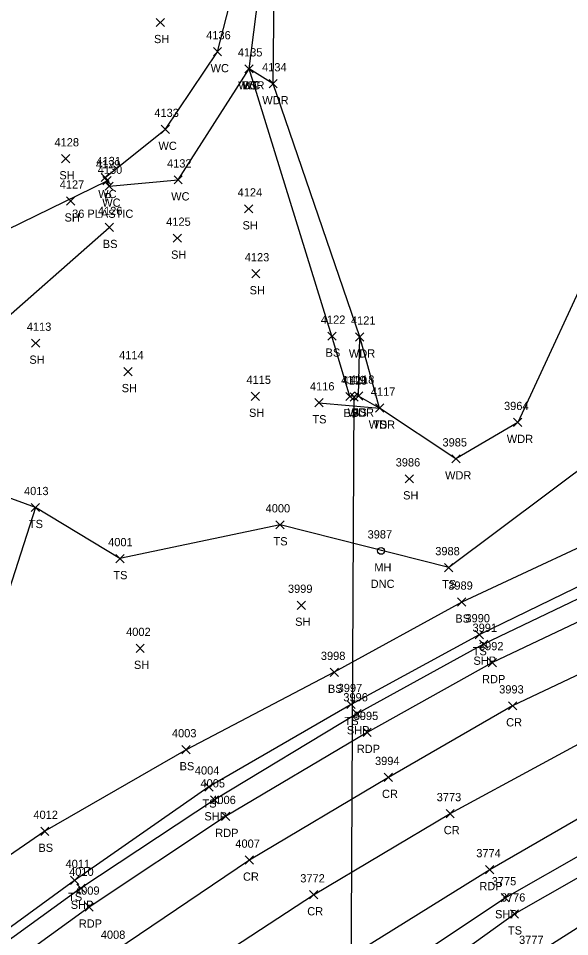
# Model space of a CAD drawing. Extents: x 1623612 to 1625808, y 621345 to 627748.
# Drawn here: x 1625217 to 1625350.8, y 627315.5 to 627538.2 of the extents above; entities that cross this region are included whole.
import ezdxf

# ---------------------------------------------------------------- set-up
doc = ezdxf.new("R2010")
doc.units = 0
for name, color, linetype in [('D_A', 7, 'Continuous'), ('D_C', 7, 'Continuous'), ('D_I', 7, 'Continuous'), ('D_TIC', 7, 'Continuous'), ('DCP', 7, 'Continuous'), ('L_A', 7, 'Continuous'), ('L_I', 7, 'Continuous'), ('L_TIC', 7, 'Continuous'), ('LAWA', 7, 'Continuous'), ('LAWE', 7, 'Continuous'), ('LELB', 7, 'Continuous'), ('LSOGP', 7, 'Continuous'), ('P_A', 7, 'Continuous'), ('P_I', 7, 'Continuous'), ('P_TIC', 7, 'Continuous'), ('PET', 7, 'Continuous'), ('PRC', 7, 'Continuous'), ('PSP', 7, 'Continuous'), ('U_A', 7, 'Continuous'), ('U_C', 7, 'Continuous'), ('U_I', 7, 'Continuous'), ('UUMH', 7, 'Continuous')]:
    doc.layers.add(name, color=color, linetype=linetype)

msp = doc.modelspace()

# ---------------------------------------------------------------- linework, layer by layer
at = {"layer": 'D_TIC'}
for points in [[(1625237.51, 627497.84), (1625239.51, 627499.84)], [(1625239.51, 627497.84), (1625237.51, 627499.84)], [(1625297.49, 627445.36), (1625299.49, 627447.36)], [(1625299.49, 627445.36), (1625297.49, 627447.36)]]:
    msp.add_lwpolyline(points, dxfattribs=at)
at = {"layer": 'DCP'}
for points in [[(1625062.29, 627412.82), (1625238.51, 627498.84)], [(1625297.51, 627253.9), (1625298.49, 627446.36)]]:
    msp.add_lwpolyline(points, dxfattribs=at)
at = {"layer": 'L_TIC'}
for points in [[(1625250.42, 627536.22), (1625252.42, 627538.22)], [(1625252.42, 627536.22), (1625250.42, 627538.22)], [(1625264.33, 627529.15), (1625266.33, 627531.15)], [(1625266.33, 627529.15), (1625264.33, 627531.15)], [(1625271.97, 627524.99), (1625273.97, 627526.99)], [(1625273.97, 627524.99), (1625271.97, 627526.99)], [(1625271.97, 627524.99), (1625273.97, 627526.99)], [(1625273.97, 627524.99), (1625271.97, 627526.99)], [(1625271.97, 627524.99), (1625273.97, 627526.99)], [(1625273.97, 627524.99), (1625271.97, 627526.99)], [(1625277.83, 627521.38), (1625279.83, 627523.38)], [(1625279.83, 627521.38), (1625277.83, 627523.38)], [(1625251.68, 627510.31), (1625253.68, 627512.31)], [(1625253.68, 627510.31), (1625251.68, 627512.31)], [(1625227.45, 627503.17), (1625229.45, 627505.17)], [(1625229.45, 627503.17), (1625227.45, 627505.17)], [(1625237.06, 627498.63), (1625239.06, 627500.63)], [(1625239.06, 627498.63), (1625237.06, 627500.63)], [(1625254.77, 627498.05), (1625256.77, 627500.05)], [(1625256.77, 627498.05), (1625254.77, 627500.05)], [(1625238.03, 627496.52), (1625240.03, 627498.52)], [(1625240.03, 627496.52), (1625238.03, 627498.52)], [(1625238.03, 627496.52), (1625240.03, 627498.52)], [(1625240.03, 627496.52), (1625238.03, 627498.52)], [(1625228.71, 627492.93), (1625230.71, 627494.93)], [(1625230.71, 627492.93), (1625228.71, 627494.93)], [(1625271.91, 627491.02), (1625273.91, 627493.02)], [(1625273.91, 627491.02), (1625271.91, 627493.02)], [(1625238.04, 627486.51), (1625240.04, 627488.51)], [(1625240.04, 627486.51), (1625238.04, 627488.51)], [(1625254.56, 627483.91), (1625256.56, 627485.91)], [(1625256.56, 627483.91), (1625254.56, 627485.91)], [(1625273.63, 627475.28), (1625275.63, 627477.28)], [(1625275.63, 627475.28), (1625273.63, 627477.28)], [(1625292.11, 627460.14), (1625294.11, 627462.14)], [(1625294.11, 627460.14), (1625292.11, 627462.14)], [(1625298.84, 627459.95), (1625300.84, 627461.95)], [(1625300.84, 627459.95), (1625298.84, 627461.95)], [(1625220.17, 627458.43), (1625222.17, 627460.43)], [(1625222.17, 627458.43), (1625220.17, 627460.43)], [(1625242.58, 627451.54), (1625244.58, 627453.54)], [(1625244.58, 627451.54), (1625242.58, 627453.54)], [(1625273.48, 627445.55), (1625275.48, 627447.55)], [(1625275.48, 627445.55), (1625273.48, 627447.55)], [(1625296.46, 627445.5), (1625298.46, 627447.5)], [(1625298.46, 627445.5), (1625296.46, 627447.5)], [(1625298.56, 627445.61), (1625300.56, 627447.61)], [(1625300.56, 627445.61), (1625298.56, 627447.61)], [(1625298.56, 627445.61), (1625300.56, 627447.61)], [(1625300.56, 627445.61), (1625298.56, 627447.61)], [(1625288.94, 627443.97), (1625290.94, 627445.97)], [(1625290.94, 627443.97), (1625288.94, 627445.97)], [(1625303.67, 627442.68), (1625305.67, 627444.68)], [(1625305.67, 627442.68), (1625303.67, 627444.68)], [(1625303.67, 627442.68), (1625305.67, 627444.68)], [(1625305.67, 627442.68), (1625303.67, 627444.68)], [(1625337.18, 627439.21), (1625339.18, 627441.21)], [(1625339.18, 627439.21), (1625337.18, 627441.21)], [(1625322.19, 627430.37), (1625324.19, 627432.37)], [(1625324.19, 627430.37), (1625322.19, 627432.37)], [(1625310.88, 627425.52), (1625312.88, 627427.52)], [(1625312.88, 627425.52), (1625310.88, 627427.52)], [(1625220.13, 627418.57), (1625222.13, 627420.57)], [(1625222.13, 627418.57), (1625220.13, 627420.57)], [(1625220.13, 627418.57), (1625222.13, 627420.57)], [(1625222.13, 627418.57), (1625220.13, 627420.57)], [(1625279.5, 627414.37), (1625281.5, 627416.37)], [(1625281.5, 627414.37), (1625279.5, 627416.37)], [(1625240.63, 627406.16), (1625242.63, 627408.16)], [(1625242.63, 627406.16), (1625240.63, 627408.16)], [(1625320.43, 627403.98), (1625322.43, 627405.98)], [(1625322.43, 627403.98), (1625320.43, 627405.98)], [(1625323.6, 627395.63), (1625325.6, 627397.63)], [(1625325.6, 627395.63), (1625323.6, 627397.63)], [(1625284.69, 627394.86), (1625286.69, 627396.86)], [(1625286.69, 627394.86), (1625284.69, 627396.86)], [(1625327.85, 627387.71), (1625329.85, 627389.71)], [(1625329.85, 627387.71), (1625327.85, 627389.71)], [(1625245.56, 627384.4), (1625247.56, 627386.4)], [(1625247.56, 627384.4), (1625245.56, 627386.4)], [(1625292.67, 627378.58), (1625294.67, 627380.58)], [(1625294.67, 627378.58), (1625292.67, 627380.58)], [(1625296.75, 627370.78), (1625298.75, 627372.78)], [(1625298.75, 627370.78), (1625296.75, 627372.78)], [(1625256.68, 627359.81), (1625258.68, 627361.81)], [(1625258.68, 627359.81), (1625256.68, 627361.81)], [(1625262.25, 627350.78), (1625264.25, 627352.78)], [(1625264.25, 627350.78), (1625262.25, 627352.78)], [(1625222.41, 627340.02), (1625224.41, 627342.02)], [(1625224.41, 627340.02), (1625222.41, 627342.02)], [(1625229.65, 627328.1), (1625231.65, 627330.1)], [(1625231.65, 627328.1), (1625229.65, 627330.1)], [(1625336.41, 627319.97), (1625338.41, 627321.97)], [(1625338.41, 627319.97), (1625336.41, 627321.97)]]:
    msp.add_lwpolyline(points, dxfattribs=at)
at = {"layer": 'LAWA'}
msp.add_lwpolyline([(1625776.12, 627510.47), (1625741.5, 627522.61), (1625709.32, 627525.44), (1625672.6, 627530.62), (1625631.44, 627521.88), (1625594.09, 627519.48), (1625541.78, 627524.14), (1625504, 627515.37), (1625452.85, 627501.7), (1625394.28, 627497.83), (1625358.56, 627483.98), (1625338.18, 627440.21), (1625323.19, 627431.37), (1625304.67, 627443.68), (1625299.56, 627446.61), (1625299.84, 627460.95), (1625278.83, 627522.38), (1625272.97, 627525.99)], dxfattribs=at)
at = {"layer": 'LAWE'}
for points in [[(1625239.03, 627497.52), (1625238.06, 627499.63), (1625252.68, 627511.31), (1625265.33, 627530.15), (1625274.72, 627566.65), (1625281.4, 627608.5), (1625289.25, 627648.82), (1625293.71, 627682.25), (1625297.74, 627712.15)], [(1625239.03, 627497.52), (1625255.77, 627499.05), (1625272.97, 627525.99), (1625278.19, 627566.71), (1625283.73, 627607.82), (1625292.18, 627648.48), (1625296.52, 627682.66), (1625299.97, 627711.37)]]:
    msp.add_lwpolyline(points, dxfattribs=at)
at = {"layer": 'LELB'}
for points in [[(1625372.28, 627409.75), (1625328.85, 627388.71), (1625297.75, 627371.78), (1625263.25, 627351.78), (1625230.65, 627329.1), (1625192.17, 627301.11), (1625167.95, 627280.99), (1625146.72, 627261.51), (1625115.03, 627231.95), (1625100.27, 627217.86), (1625086.73, 627226.42), (1625099.85, 627264.36), (1625110.36, 627291.47), (1625123.03, 627324.24), (1625138.33, 627365.32), (1625149.22, 627400.11), (1625166.29, 627438.85), (1625173.02, 627469.22), (1625178.77, 627488.11), (1625188.89, 627523.13), (1625197.3, 627554.83)], [(1625299.56, 627446.61), (1625297.46, 627446.5), (1625293.11, 627461.14), (1625272.97, 627525.99)], [(1625452.85, 627501.7), (1625422.04, 627480.13), (1625403.16, 627461.47), (1625391.04, 627454.62), (1625372.15, 627447.63), (1625358.13, 627432.41), (1625321.43, 627404.98), (1625280.5, 627415.37), (1625241.63, 627407.16), (1625221.13, 627419.57), (1625212.45, 627392.88), (1625201.4, 627362.25), (1625193.63, 627336.03), (1625182.54, 627313.02), (1625161.13, 627290.14), (1625138.48, 627273.13)], [(1625133.79, 627254.9), (1625111.98, 627240.01), (1625101.06, 627227.21), (1625095.52, 627229.82), (1625109.84, 627261.79), (1625128.81, 627280.01), (1625155.03, 627318.41), (1625177.57, 627352.11), (1625196.11, 627392.11), (1625207.11, 627424.62), (1625209.77, 627461.79), (1625239.04, 627487.51)], [(1625289.94, 627444.97), (1625304.67, 627443.68)], [(1625221.13, 627419.57), (1625207.11, 627424.62), (1625188.59, 627430.56)], [(1625379.89, 627425.39), (1625369.39, 627417.46), (1625324.6, 627396.63), (1625293.67, 627379.58), (1625257.68, 627360.81), (1625223.41, 627341.02), (1625182.54, 627313.02)], [(1625111, 627101.13), (1625130.83, 627129.7), (1625156.28, 627161.64), (1625181.98, 627191.95), (1625204.33, 627215.18), (1625231.94, 627241.85), (1625257.57, 627263.61), (1625279.76, 627280.38), (1625303.46, 627296.59), (1625337.41, 627320.97), (1625377.29, 627343.7), (1625408.84, 627358.2), (1625449.74, 627375.28), (1625489.49, 627389.68), (1625533.09, 627402.6), (1625571.15, 627412.06), (1625624.18, 627419.27), (1625663.51, 627421.72), (1625706.22, 627423.86), (1625739.39, 627422.48), (1625780.2, 627420.23)], [(1625173.57, 627103.31), (1625198.3, 627138.01), (1625235.5, 627181.26), (1625257.15, 627208.81), (1625262.64, 627212.84), (1625293.35, 627251.67), (1625296.85, 627253.7), (1625299.51, 627255.19), (1625302.1, 627256.94), (1625301.55, 627257.93), (1625312.93, 627281.54), (1625341.78, 627310.69), (1625378.89, 627334.21), (1625411.91, 627351.77), (1625451.38, 627369.19), (1625491.07, 627383.46), (1625534.23, 627395.83), (1625572.47, 627404.98), (1625624.05, 627411.53), (1625663.08, 627414.27), (1625705.62, 627414.88), (1625729.22, 627414.11), (1625728.31, 627412.09)]]:
    msp.add_lwpolyline(points, dxfattribs=at)
at = {"layer": 'LSOGP'}
msp.add_lwpolyline([(1625358.56, 627483.98), (1625338.18, 627440.21), (1625323.19, 627431.37), (1625304.67, 627443.68), (1625299.84, 627460.95), (1625278.83, 627522.38), (1625279.29, 627566.66)], dxfattribs=at)
at = {"layer": 'P_TIC'}
for points in [[(1625328.92, 627385.4), (1625330.92, 627387.4)], [(1625330.92, 627385.4), (1625328.92, 627387.4)], [(1625331.04, 627380.93), (1625333.04, 627382.93)], [(1625333.04, 627380.93), (1625331.04, 627382.93)], [(1625298.17, 627368.53), (1625300.17, 627370.53)], [(1625300.17, 627368.53), (1625298.17, 627370.53)], [(1625335.95, 627370.45), (1625337.95, 627372.45)], [(1625337.95, 627370.45), (1625335.95, 627372.45)], [(1625300.64, 627364.01), (1625302.64, 627366.01)], [(1625302.64, 627364.01), (1625300.64, 627366.01)], [(1625305.81, 627353.09), (1625307.81, 627355.09)], [(1625307.81, 627353.09), (1625305.81, 627355.09)], [(1625263.6, 627347.65), (1625265.6, 627349.65)], [(1625265.6, 627347.65), (1625263.6, 627349.65)], [(1625320.79, 627344.31), (1625322.79, 627346.31)], [(1625322.79, 627344.31), (1625320.79, 627346.31)], [(1625266.28, 627343.62), (1625268.28, 627345.62)], [(1625268.28, 627343.62), (1625266.28, 627345.62)], [(1625272.07, 627333.02), (1625274.07, 627335.02)], [(1625274.07, 627333.02), (1625272.07, 627335.02)], [(1625330.39, 627330.71), (1625332.39, 627332.71)], [(1625332.39, 627330.71), (1625330.39, 627332.71)], [(1625231.17, 627326.19), (1625233.17, 627328.19)], [(1625233.17, 627326.19), (1625231.17, 627328.19)], [(1625287.66, 627324.61), (1625289.66, 627326.61)], [(1625289.66, 627324.61), (1625287.66, 627326.61)], [(1625334.15, 627323.9), (1625336.15, 627325.9)], [(1625336.15, 627323.9), (1625334.15, 627325.9)], [(1625233.17, 627321.63), (1625235.17, 627323.63)], [(1625235.17, 627321.63), (1625233.17, 627323.63)]]:
    msp.add_lwpolyline(points, dxfattribs=at)
at = {"layer": 'PET'}
for points in [[(1625085.4, 627094.25), (1625110.27, 627129.17), (1625131.75, 627158.75), (1625155.63, 627186.85), (1625182.85, 627215.54), (1625208.2, 627240.19), (1625221.56, 627252.36), (1625248.45, 627276.07), (1625271.93, 627291.03), (1625296.8, 627310.27), (1625331.39, 627331.71), (1625373.16, 627355.88), (1625402.91, 627369.89), (1625447, 627387.72), (1625485.15, 627401.55), (1625532.49, 627414.31), (1625569.15, 627422.13), (1625624.7, 627430.37), (1625663.96, 627433.7), (1625707.55, 627434.84), (1625740.73, 627434.04), (1625783.87, 627430.92)], [(1625375.59, 627402.57), (1625332.04, 627381.93), (1625301.64, 627365.01), (1625267.28, 627344.62), (1625234.17, 627322.63), (1625196.65, 627295.4)]]:
    msp.add_lwpolyline(points, dxfattribs=at)
at = {"layer": 'PRC'}
for points in [[(1625792.68, 627459.81), (1625752.01, 627462.3), (1625712.17, 627462.44), (1625670.97, 627461.5), (1625632.33, 627458.42), (1625595.29, 627453.83), (1625553.12, 627446.65), (1625514.39, 627438.17), (1625484.1, 627430.19), (1625416.72, 627407.88), (1625381.04, 627392.28), (1625336.95, 627371.45), (1625306.81, 627354.09), (1625273.07, 627334.02), (1625240.42, 627311.93), (1625203.88, 627285.7), (1625180.94, 627267.49), (1625158.54, 627247.08), (1625127.91, 627216.66), (1625109.17, 627195.82), (1625080.92, 627162.34), (1625061.45, 627135.11), (1625041.85, 627107.05)], [(1625234.51, 627287.77), (1625260.57, 627307.21), (1625288.66, 627325.61), (1625321.79, 627345.31), (1625366.63, 627369.57), (1625395.66, 627383.57), (1625442.85, 627402.94), (1625480.48, 627416.13), (1625529.86, 627429.74), (1625566.79, 627436.89), (1625625.45, 627445.69), (1625663.4, 627448.8), (1625708.22, 627450.49), (1625743.86, 627449.51), (1625788.41, 627445.83)]]:
    msp.add_lwpolyline(points, dxfattribs=at)
at = {"layer": 'PSP'}
for points in [[(1625108.38, 627102.81), (1625128.19, 627131.96), (1625153.78, 627164.79), (1625179.21, 627194.48), (1625201.56, 627217.89), (1625229.72, 627244.56), (1625255.64, 627267.13), (1625276.98, 627284.12), (1625300.33, 627301.71), (1625335.15, 627324.9), (1625375.44, 627347.8), (1625406.32, 627362.88), (1625448.69, 627381.31), (1625487.83, 627394.48), (1625532.78, 627406.83), (1625570.78, 627414.59), (1625624.36, 627422.79), (1625663.55, 627425.73), (1625706.52, 627426.77), (1625740.26, 627425.81), (1625780.96, 627423.03)], [(1625373.8, 627407.45), (1625329.92, 627386.4), (1625299.17, 627369.53), (1625264.6, 627348.65), (1625232.17, 627327.19), (1625193.27, 627299.11)]]:
    msp.add_lwpolyline(points, dxfattribs=at)
at = {"layer": 'UUMH'}
for p, q in [((1625305.01, 627409.05), (1625305.01, 627409.05)), ((1625305.84, 627409.05), (1625305.84, 627409.05))]:
    msp.add_line(p, q, dxfattribs=at)
msp.add_circle((1625305.01, 627409.05), 0.833, dxfattribs=at)

# ---------------------------------------------------------------- texts
at = {"layer": 'D_A'}
for p in [(1625237.88, 627493.84), (1625297.87, 627441.36)]:
    msp.add_text('P', height=2, dxfattribs=at).set_placement(p)
at = {"layer": 'D_C'}
msp.add_text('36 PLASTIC', height=2, dxfattribs=at).set_placement((1625230.03, 627489.84))
at = {"layer": 'D_I'}
for s, p in [('4129', (1625235.8, 627501.84)), ('4120', (1625295.71, 627449.36))]:
    msp.add_text(s, height=2, dxfattribs=at).set_placement(p)
at = {"layer": 'L_A'}
for s, p in [('SH', (1625249.91, 627532.22)), ('WC', (1625263.64, 627525.15)), ('WDR', (1625270.33, 627520.99)), ('WC', (1625271.27, 627520.99)), ('BS', (1625271.41, 627520.99)), ('WDR', (1625276.19, 627517.38)), ('WC', (1625250.99, 627506.31)), ('SH', (1625226.94, 627499.17)), ('WC', (1625236.37, 627494.63)), ('WC', (1625254.07, 627494.05)), ('WC', (1625237.34, 627492.52)), ('WC', (1625237.34, 627492.52)), ('SH', (1625228.2, 627488.93)), ('SH', (1625271.4, 627487.02)), ('BS', (1625237.48, 627482.51)), ('SH', (1625254.05, 627479.91)), ('SH', (1625273.12, 627471.28)), ('BS', (1625291.55, 627456.14)), ('WDR', (1625297.2, 627455.95)), ('SH', (1625219.66, 627454.43)), ('SH', (1625242.07, 627447.54)), ('SH', (1625272.97, 627441.55)), ('TS', (1625288.35, 627439.97)), ('BS', (1625295.9, 627441.5)), ('WDR', (1625296.92, 627441.61)), ('BS', (1625298, 627441.61)), ('WDR', (1625302.03, 627438.68)), ('TS', (1625303.08, 627438.68)), ('WDR', (1625335.54, 627435.21)), ('WDR', (1625320.55, 627426.37)), ('SH', (1625310.37, 627421.52)), ('TS', (1625219.54, 627414.57)), ('TS', (1625219.54, 627414.57)), ('TS', (1625278.91, 627410.37)), ('TS', (1625240.04, 627402.16)), ('TS', (1625319.83, 627399.98)), ('SH', (1625284.17, 627390.86)), ('BS', (1625323.04, 627391.63)), ('TS', (1625327.26, 627383.71)), ('SH', (1625245.04, 627380.4)), ('BS', (1625292.12, 627374.58)), ('TS', (1625296.16, 627366.78)), ('BS', (1625256.12, 627355.81)), ('TS', (1625261.66, 627346.78)), ('BS', (1625221.85, 627336.02)), ('TS', (1625229.06, 627324.1)), ('TS', (1625335.82, 627315.97))]:
    msp.add_text(s, height=2, dxfattribs=at).set_placement(p)
at = {"layer": 'L_I'}
for s, p in [('4136', (1625262.58, 627533.15)), ('4135', (1625270.27, 627528.99)), ('4135', (1625270.27, 627528.99)), ('4135', (1625270.27, 627528.99)), ('4134', (1625276.14, 627525.38)), ('4133', (1625249.99, 627514.31)), ('4128', (1625225.76, 627507.17)), ('4131', (1625235.93, 627502.63)), ('4130', (1625236.25, 627500.52)), ('4130', (1625236.25, 627500.52)), ('4132', (1625253.07, 627502.05)), ('4127', (1625227.02, 627496.93)), ('4124', (1625270.21, 627495.02)), ('4126', (1625236.3, 627490.51)), ('4125', (1625252.87, 627487.91)), ('4123', (1625271.94, 627479.28)), ('4113', (1625219.04, 627462.43)), ('4122', (1625290.41, 627464.14)), ('4121', (1625297.71, 627463.95)), ('4114', (1625241.45, 627455.54)), ('4115', (1625272.35, 627449.55)), ('4119', (1625295.33, 627449.5)), ('4118', (1625297.43, 627449.61)), ('4118', (1625297.43, 627449.61)), ('4116', (1625287.76, 627447.97)), ('4117', (1625302.54, 627446.68)), ('4117', (1625302.54, 627446.68)), ('3964', (1625334.87, 627443.21)), ('3985', (1625319.93, 627434.37)), ('3986', (1625308.57, 627429.52)), ('4013', (1625218.36, 627422.57)), ('4013', (1625218.36, 627422.57)), ('4000', (1625277, 627418.37)), ('4001', (1625238.78, 627410.16)), ('3988', (1625318.17, 627407.98)), ('3999', (1625282.42, 627398.86)), ('3989', (1625321.33, 627399.63)), ('3990', (1625325.5, 627391.71)), ('4002', (1625243.14, 627388.4)), ('3998', (1625290.41, 627382.58)), ('3997', (1625294.49, 627374.78)), ('4003', (1625254.26, 627363.81)), ('4004', (1625259.83, 627354.78)), ('4012', (1625220.64, 627344.02)), ('4011', (1625228.44, 627332.1)), ('3776', (1625334.09, 627323.97)), ('3777', (1625338.52, 627313.69))]:
    msp.add_text(s, height=2, dxfattribs=at).set_placement(p)
at = {"layer": 'P_A'}
for s, p in [('SHP', (1625327.45, 627381.4)), ('RDP', (1625329.53, 627376.93)), ('CR', (1625335.38, 627366.45)), ('SHP', (1625296.71, 627364.53)), ('RDP', (1625299.13, 627360.01)), ('CR', (1625305.25, 627349.09)), ('SHP', (1625262.14, 627343.65)), ('RDP', (1625264.77, 627339.62)), ('CR', (1625320.23, 627340.31)), ('CR', (1625271.5, 627329.02)), ('RDP', (1625328.88, 627326.71)), ('SHP', (1625229.7, 627322.19)), ('CR', (1625287.1, 627320.61)), ('SHP', (1625332.68, 627319.9)), ('RDP', (1625231.65, 627317.63))]:
    msp.add_text(s, height=2, dxfattribs=at).set_placement(p)
at = {"layer": 'P_I'}
for s, p in [('3991', (1625327.22, 627389.4)), ('3992', (1625328.78, 627384.93)), ('3993', (1625333.69, 627374.45)), ('3996', (1625295.86, 627372.53)), ('3995', (1625298.38, 627368.01)), ('3994', (1625303.55, 627357.09)), ('4005', (1625261.19, 627351.65)), ('4006', (1625263.81, 627347.62)), ('3773', (1625318.53, 627348.31)), ('4007', (1625269.65, 627337.02)), ('3774', (1625328.13, 627334.71)), ('4010', (1625229.31, 627330.19)), ('3772', (1625285.41, 627328.61)), ('3775', (1625331.89, 627327.9)), ('4009', (1625230.74, 627325.63)), ('4008', (1625237, 627314.93))]:
    msp.add_text(s, height=2, dxfattribs=at).set_placement(p)
at = {"layer": 'U_A'}
msp.add_text('MH', height=2, dxfattribs=at).set_placement((1625303.37, 627404.05))
at = {"layer": 'U_C'}
msp.add_text('DNC', height=2, dxfattribs=at).set_placement((1625302.5, 627400.05))
at = {"layer": 'U_I'}
msp.add_text('3987', height=2, dxfattribs=at).set_placement((1625301.75, 627412.05))

doc.saveas('drawing.dxf')
